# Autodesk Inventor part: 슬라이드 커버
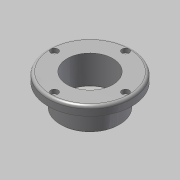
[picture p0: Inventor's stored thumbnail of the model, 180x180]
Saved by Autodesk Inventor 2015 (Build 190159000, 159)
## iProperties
Created: 2015-10
Part Number: 슬라이드 커버
Document SubType Name: Modeling
Designer: mdu
Density: 7.86 g/cm^3
Material: 강철, 연강
Mass: 598.523 g
Surface Area: 229.996 cm^2
Volume: 76.148 cm^3
Appearance: Steel
Author: mdu
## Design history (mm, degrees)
sketch "스케치1"
  geometry: C1 r 46 at (0, -39.25) reference; C2 r 32.5 at (0, -39.25) reference; 1 further point
  node "참조1"
  node "참조2"
extrude "돌출1" new body sketch "스케치1" distance "d0" = 10; taper "d1" = 0 deg
extrude "돌출2" join sketch "스케치1" distance "d2" = 25; taper "d3" = 0 deg
hole "구멍1" diameter "d6" = 50; stored, may be unused: countersink angle "d10" = 90 deg, drill point angle "d12" = 118 deg; dims "d4" = 10, "d5" = 10, "d7" = 6, "d8" = 4, "d9" = 2, "d11" = 8
sketch "스케치2"
  geometry: C1 r 46 at (0, 0) reference; C2 r 1.621 at (0, 39) reference; C3 r 1.621 at (39, 0) reference; C4 r 1.621 at (0, -39) reference; C5 r 1.621 at (-39, 0) reference; C6 r 33.5 at (0, 0) reference; 1 further point
hole "구멍2" sketch "스케치2" at (0, 39) diameter "d13" = 4.5; stored, may be unused: countersink angle "d17" = 90 deg, drill point angle "d19" = 118 deg; dims "d14" = 6, "d15" = 8, "d16" = 4.4, "d18" = 8
fillet "모깎기1" dims "d23" = 3
chamfer "모따기1" distance "d24" = 1; stored, may be unused: second distance "d25" = 2, angle "d26" = 45 deg
sketch "스케치3"
  geometry: C1 r 25 at (0, 0); C2 r 30 at (0, 0); C3 r 26 at (0, 0) reference; 1 further point
  constraints: 2 centre point, 2 coincident
  dimensions: "d27" = 60 diameter of C2
extrude "돌출3" cut sketch "스케치3" distance "d28" = 3; taper "d29" = 0 deg
chamfer "모따기2" distance "d30" = 1; stored, may be unused: second distance "d31" = 2, angle "d32" = 45 deg
node "솔리드1"
pattern_circular "원형 패턴1" dims angle "d21" = 360 deg
node "참조3"
